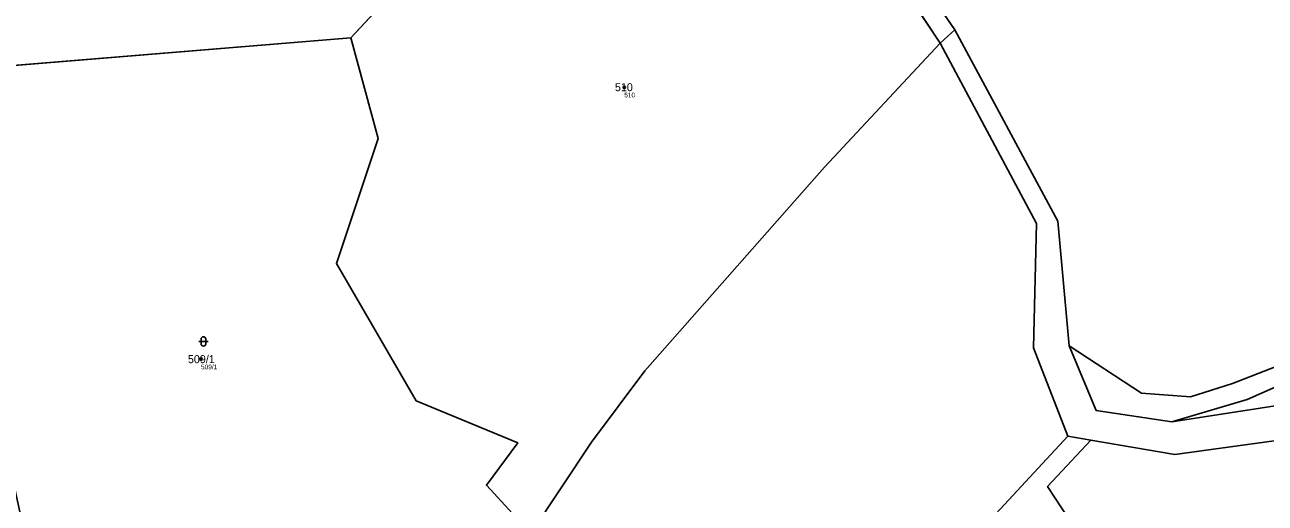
# Model space of a CAD drawing. Extents: x -766177 to -763254, y -1057727 to -1053915.
# Drawn here: x -765543.3 to -765280, y -1056408.2 to -1056306.7 of the extents above; entities that cross this region are included whole.
import ezdxf

# ---------------------------------------------------------------- set-up
doc = ezdxf.new("R2010")
doc.units = 0
for name, color, linetype in [('Vrstva 1', 7, 'Continuous'), ('Vrstva 2', 7, 'Continuous'), ('Vrstva 3', 7, 'Continuous'), ('Vrstva 50', 7, 'Continuous'), ('Vrstva 51', 7, 'Continuous')]:
    doc.layers.add(name, color=color, linetype=linetype)

msp = doc.modelspace()

# ---------------------------------------------------------------- linework, layer by layer
at = {"layer": 'Vrstva 1'}
for p, q in [((-765386.27, -1056249.12), (-765345.84, -1056307.83)), ((-765388.1, -1056251.45), (-765349, -1056310.65)), ((-765474.11, -1056309.49), (-765448.97, -1056282.49)), ((-765349, -1056310.65), (-765345.84, -1056307.83)), ((-765474.11, -1056309.49), (-765567.96, -1056317.23)), ((-765316.95, -1056394.87), (-765321.86, -1056394.04))]:
    msp.add_line(p, q, dxfattribs=at)
for points in [[(-765345.84, -1056307.83), (-765323.95, -1056348.38), (-765321.56, -1056374.82)], [(-765321.56, -1056374.82), (-765306.23, -1056384.88), (-765295.81, -1056385.68), (-765286.92, -1056382.87), (-765260.36, -1056372.5), (-765238.67, -1056362.41), (-765227.95, -1056355.32), (-765207.53, -1056346.09), (-765146.85, -1056327.24), (-765129.63, -1056323.56), (-765096.36, -1056318.28), (-765081.56, -1056314.03), (-765067.23, -1056307.39), (-765054.47, -1056309.45), (-765052.85, -1056313.32)], [(-765435.92, -1056414.68), (-765445.32, -1056404.44), (-765438.68, -1056395.45), (-765460.21, -1056386.5), (-765477.15, -1056357.39), (-765468.33, -1056330.83), (-765474.11, -1056309.49)], [(-765349, -1056310.65), (-765373.52, -1056336.95), (-765411.65, -1056380.15), (-765423, -1056395.3), (-765435.92, -1056414.68)], [(-765321.86, -1056394.04), (-765329.13, -1056375.26), (-765328.53, -1056348.88), (-765349, -1056310.65)], [(-765210.51, -1056351.35), (-765223.24, -1056357.44), (-765235.08, -1056364.75), (-765283.8, -1056386.26), (-765299.76, -1056390.99)], [(-765299.76, -1056390.99), (-765238.46, -1056381.53), (-765203.63, -1056371.77)], [(-765321.56, -1056374.82), (-765315.84, -1056388.59), (-765299.76, -1056390.99)], [(-765229.45, -1056386.41), (-765244.61, -1056390.39), (-765299.12, -1056397.88), (-765316.95, -1056394.87)], [(-765321.86, -1056394.04), (-765355.15, -1056429.86), (-765368.34, -1056445.7)], [(-765289, -1056461.31), (-765326.17, -1056404.67), (-765316.95, -1056394.87)]]:
    msp.add_lwpolyline(points, dxfattribs=at)
at = {"layer": 'Vrstva 3'}
for p, q in [((-765506.401, -1056373.921), (-765504.399, -1056373.921)), ((-765505.901, -1056373.421), (-765505.901, -1056374.422)), ((-765504.899, -1056374.422), (-765504.899, -1056373.421))]:
    msp.add_line(p, q, dxfattribs=at)
for centre, start, end in [((-765505.4, -1056373.4209), 0, 180), ((-765505.4, -1056374.4209), 180, 359.9878861)]:
    msp.add_arc(centre, 0.5, start, end, dxfattribs=at)
at = {"layer": 'Vrstva 50'}
for centre in [(-765416.05, -1056319.97994), (-765505.92, -1056377.67994)]:
    msp.add_circle(centre, 0.25, dxfattribs=at)
at = {"layer": 'Vrstva 51'}
for points in [[(-765435.92, -1056414.68), (-765423, -1056395.3), (-765411.65, -1056380.15), (-765373.52, -1056336.95), (-765349, -1056310.65), (-765388.1, -1056251.45), (-765396.12, -1056243.1), (-765407.66, -1056250.64), (-765422.65, -1056261.47), (-765448.97, -1056282.49), (-765474.11, -1056309.49), (-765468.33, -1056330.83), (-765477.15, -1056357.39), (-765460.21, -1056386.5), (-765438.68, -1056395.45), (-765445.32, -1056404.44)], [(-765388.1, -1056251.45), (-765349, -1056310.65), (-765345.84, -1056307.83), (-765386.27, -1056249.12)], [(-765468.33, -1056330.83), (-765474.11, -1056309.49), (-765567.96, -1056317.23), (-765548.73, -1056390.56), (-765543.68, -1056413.34), (-765534.06, -1056455.54), (-765435.92, -1056414.68), (-765445.32, -1056404.44), (-765438.68, -1056395.45), (-765460.21, -1056386.5), (-765477.15, -1056357.39)], [(-765423, -1056395.3), (-765435.92, -1056414.68), (-765433.23, -1056424.78), (-765440.57, -1056439.64), (-765438.26, -1056454.88), (-765442.97, -1056470.36), (-765453.21, -1056483.34), (-765444.45, -1056519.12), (-765432.41, -1056515.03), (-765378.44, -1056463.18), (-765371.98, -1056451.16), (-765368.34, -1056445.7), (-765355.15, -1056429.86), (-765321.86, -1056394.04), (-765329.13, -1056375.26), (-765328.53, -1056348.88), (-765349, -1056310.65), (-765373.52, -1056336.95), (-765411.65, -1056380.15)], [(-765210.51, -1056351.35), (-765223.24, -1056357.44), (-765235.08, -1056364.75), (-765283.8, -1056386.26), (-765299.76, -1056390.99), (-765238.46, -1056381.53), (-765203.63, -1056371.77), (-765204.4, -1056369.49)], [(-765245.76, -1056449.78), (-765235.4, -1056443.62), (-765232.31, -1056448.66), (-765208.88, -1056427.15), (-765229.45, -1056386.41), (-765244.61, -1056390.39), (-765299.12, -1056397.88), (-765316.95, -1056394.87), (-765326.17, -1056404.67), (-765289, -1056461.31), (-765276.08, -1056479.61), (-765269.29, -1056474.33), (-765265.9, -1056479.49), (-765241.36, -1056456.97)], [(-765321.86, -1056394.04), (-765355.15, -1056429.86), (-765368.34, -1056445.7), (-765333.87, -1056499.31), (-765315.04, -1056483.36), (-765307.08, -1056476.62), (-765298.92, -1056469.71), (-765289, -1056461.31), (-765326.17, -1056404.67), (-765316.95, -1056394.87)]]:
    msp.add_lwpolyline(points, close=True, dxfattribs=at)
for points in [[(-765386.27, -1056249.12), (-765345.84, -1056307.83), (-765323.95, -1056348.38), (-765321.56, -1056374.82), (-765306.23, -1056384.88), (-765295.81, -1056385.68), (-765286.92, -1056382.87), (-765260.36, -1056372.5), (-765238.67, -1056362.41), (-765227.95, -1056355.32), (-765207.53, -1056346.09), (-765146.85, -1056327.24), (-765129.63, -1056323.56), (-765096.36, -1056318.28), (-765081.56, -1056314.03), (-765067.23, -1056307.39), (-765054.47, -1056309.45), (-765052.85, -1056313.32), (-765032.03, -1056299.11)], [(-765574.79, -1056286.41), (-765567.96, -1056317.23), (-765474.11, -1056309.49), (-765448.97, -1056282.49)], [(-765238.46, -1056381.53), (-765299.76, -1056390.99), (-765315.84, -1056388.59), (-765321.56, -1056374.82), (-765323.95, -1056348.38), (-765345.84, -1056307.83), (-765349, -1056310.65), (-765328.53, -1056348.88), (-765329.13, -1056375.26), (-765321.86, -1056394.04), (-765316.95, -1056394.87), (-765299.12, -1056397.88), (-765244.61, -1056390.39)], [(-765260.36, -1056372.5), (-765286.92, -1056382.87), (-765295.81, -1056385.68), (-765306.23, -1056384.88), (-765321.56, -1056374.82), (-765315.84, -1056388.59), (-765299.76, -1056390.99), (-765283.8, -1056386.26), (-765235.08, -1056364.75)]]:
    msp.add_lwpolyline(points, dxfattribs=at)

# ---------------------------------------------------------------- texts
at = {"layer": 'Vrstva 2'}
for s, p in [('510', (-765418.024, -1056320.83)), ('509/1', (-765508.693, -1056378.53))]:
    msp.add_text(s, height=1.699998, dxfattribs=at).set_placement(p)
at = {"layer": 'Vrstva 50'}
for s, p in [('510', (-765416.05, -1056322.136)), ('509/1', (-765505.92, -1056379.836))]:
    msp.add_text(s, height=0.999996, dxfattribs=at).set_placement(p)

doc.saveas('drawing.dxf')
